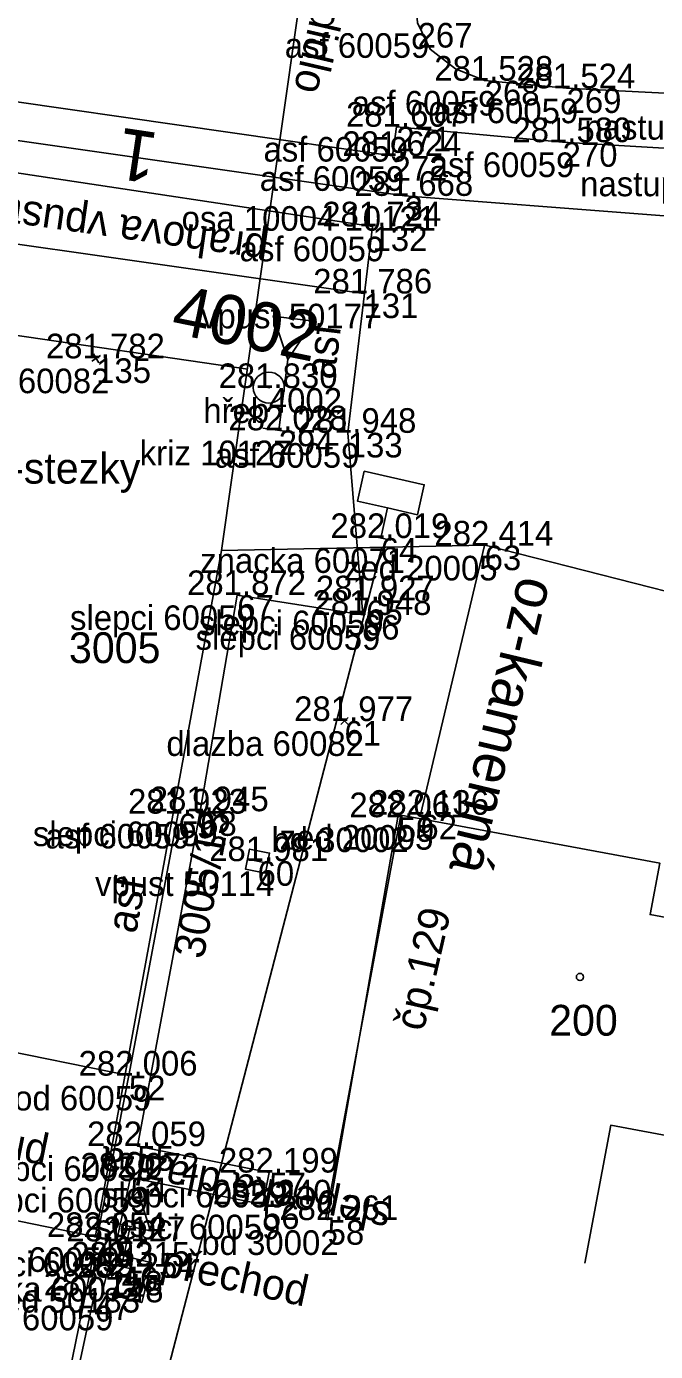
# Model space of a CAD drawing. Extents: x -728659 to -728362, y -1073110 to -1072943.
# Drawn here: x -728507.99 to -728492.66, y -1073071.85 to -1073039.57 of the extents above; entities that cross this region are included whole.
import ezdxf

# ---------------------------------------------------------------- set-up
doc = ezdxf.new("R2010")
doc.units = 0
for name, color, linetype in [('Vrstva 1', 7, 'Continuous'), ('Vrstva 13', 7, 'Continuous'), ('Vrstva 23', 7, 'Continuous'), ('Vrstva 4', 7, 'Continuous'), ('Vrstva 43', 7, 'Continuous'), ('Vrstva 47', 7, 'Continuous'), ('Vrstva 49', 7, 'Continuous'), ('Vrstva 51', 7, 'Continuous'), ('Vrstva 53', 7, 'Continuous'), ('Vrstva 55', 7, 'Continuous'), ('Vrstva 57', 7, 'Continuous'), ('Vrstva 59', 7, 'Continuous'), ('Vrstva 60', 7, 'Continuous'), ('Vrstva 61', 7, 'Continuous'), ('Vrstva 62', 7, 'Continuous'), ('Vrstva 63', 7, 'Continuous')]:
    doc.layers.add(name, color=color, linetype=linetype)

msp = doc.modelspace()

# ---------------------------------------------------------------- linework, layer by layer
at = {"layer": 'Vrstva 1'}
msp.add_lwpolyline([(-728462.112, -1073044.292), (-728486.957, -1073044.611), (-728498.776, -1073043.699), (-728511.695, -1073041.857), (-728514.393, -1073041.361), (-728535.912, -1073035.983), (-728560.369, -1073026.548)], dxfattribs=at)
at = {"layer": 'Vrstva 13'}
msp.add_line((-728496.824, -1073052.218), (-728498.391, -1073058.778), dxfattribs=at)
at = {"layer": 'Vrstva 23'}
msp.add_line((-728500.652, -1073068.652), (-728498.943, -1073058.837), dxfattribs=at)
at = {"layer": 'Vrstva 4'}
msp.add_line((-728502.231, -1073049.36), (-728501.459, -1073049.462), dxfattribs=at)
for points in [[(-728498.776, -1073043.699), (-728511.695, -1073041.857), (-728514.393, -1073041.361)], [(-728501.845, -1073049.411), (-728501.623, -1073047.687), (-728501.984, -1073046.629), (-728500.993, -1073046.754), (-728501.623, -1073047.687)]]:
    msp.add_lwpolyline(points, dxfattribs=at)
at = {"layer": 'Vrstva 43'}
for points in [[(-728499.778, -1073046.077), (-728509.811, -1073044.652), (-728514.235, -1073044.003)], [(-728502.606, -1073059.857), (-728502.556, -1073059.612), (-728502.066, -1073059.712), (-728502.166, -1073060.202), (-728502.656, -1073060.102), (-728502.606, -1073059.857), (-728502.116, -1073059.957)]]:
    msp.add_lwpolyline(points, dxfattribs=at)
at = {"layer": 'Vrstva 47'}
msp.add_lwpolyline([(-728505.905, -1073069.447), (-728504.937, -1073069.695), (-728505.185, -1073070.663), (-728506.153, -1073070.415), (-728505.905, -1073069.447)], dxfattribs=at)
at = {"layer": 'Vrstva 49'}
for p, q in [((-728506.403, -1073047.724), (-728506.191, -1073047.59)), ((-728506.364, -1073047.551), (-728506.23, -1073047.763)), ((-728500.33, -1073056.406), (-728500.154, -1073056.582)), ((-728500.33, -1073056.582), (-728500.154, -1073056.406))]:
    msp.add_line(p, q, dxfattribs=at)
at = {"layer": 'Vrstva 51'}
for p, q in [((-728499.558, -1073044.443), (-728513.906, -1073042.29)), ((-728499.601, -1073051.98), (-728499.113, -1073052.09)), ((-728505.92, -1073069.734), (-728505.432, -1073069.84))]:
    msp.add_line(p, q, dxfattribs=at)
for points in [[(-728496.482, -1073035.776), (-728497.494, -1073036.644), (-728498.316, -1073037.996), (-728498.528, -1073038.603), (-728498.459, -1073039.486), (-728498.149, -1073040.128), (-728497.533, -1073040.603), (-728496.825, -1073040.892), (-728494.827, -1073041.079), (-728486.835, -1073041.479), (-728486.937, -1073042.858), (-728494.923, -1073042.391), (-728498.977, -1073042.014), (-728499.069, -1073042.727), (-728513.553, -1073040.642)], [(-728499.794, -1073053.909), (-728500.162, -1073049.472), (-728499.558, -1073044.443)], [(-728499.357, -1073052.035), (-728499.192, -1073051.303), (-728498.46, -1073051.469), (-728498.295, -1073050.737), (-728499.758, -1073050.407), (-728499.923, -1073051.138), (-728499.192, -1073051.303)], [(-728506.273, -1073069.065), (-728505.797, -1073069.171), (-728505.457, -1073067.617), (-728502.232, -1073068.271), (-728502.075, -1073067.494), (-728505.291, -1073066.851), (-728503.761, -1073058.691), (-728502.856, -1073053.426), (-728499.794, -1073053.909), (-728499.714, -1073053.554)], [(-728505.498, -1073065.132), (-728504.293, -1073058.749)], [(-728505.498, -1073065.132), (-728512.38, -1073063.734), (-728513.171, -1073067.654), (-728506.273, -1073069.065), (-728505.498, -1073065.132)], [(-728505.676, -1073069.787), (-728505.463, -1073068.81), (-728504.975, -1073068.916), (-728505.277, -1073067.955), (-728505.952, -1073068.704), (-728505.463, -1073068.81)], [(-728518.577, -1073107.972), (-728511.413, -1073089.698), (-728508.676, -1073080.788), (-728506.273, -1073069.065)], [(-728518.469, -1073107.966), (-728511.248, -1073089.672), (-728508.568, -1073080.832), (-728506.346, -1073070.488)]]:
    msp.add_lwpolyline(points, dxfattribs=at)
at = {"layer": 'Vrstva 53'}
msp.add_lwpolyline([(-728443.68, -1073014.51), (-728493.68, -1073027.94), (-728497.54, -1073030.15), (-728499.78, -1073032.61), (-728501.19, -1073037.94), (-728503.24, -1073052.34), (-728496.81, -1073052.21), (-728491.97, -1073053.44), (-728477.97, -1073053.19), (-728434.587, -1073049.291), (-728361.73, -1073039.5)], dxfattribs=at)
at = {"layer": 'Vrstva 55'}
for p, q in [((-728502.6, -1073047.92), (-728509.9, -1073046.86)), ((-728506.32, -1073069.08), (-728503.24, -1073052.34)), ((-728504.87, -1073073.55), (-728499.33, -1073052.26))]:
    msp.add_line(p, q, dxfattribs=at)
for points in [[(-728487.98, -1073062.11), (-728492.79, -1073061.21), (-728492.55, -1073059.96), (-728498.42, -1073058.87), (-728498.87, -1073058.79), (-728500.7, -1073068.59)], [(-728494.38, -1073069.7), (-728493.75, -1073066.34), (-728490.32, -1073066.98), (-728489.74, -1073063.94), (-728488.34, -1073064.21), (-728487.98, -1073062.11)]]:
    msp.add_lwpolyline(points, dxfattribs=at)
at = {"layer": 'Vrstva 59'}
msp.add_circle((-728494.5, -1073062.729), 0.0873, dxfattribs=at)
at = {"layer": 'Vrstva 60'}
for p, q in [((-728496.825, -1073040.892), (-728496.825, -1073040.892)), ((-728494.827, -1073041.079), (-728494.827, -1073041.079)), ((-728498.977, -1073042.014), (-728498.977, -1073042.014)), ((-728494.923, -1073042.391), (-728494.923, -1073042.391)), ((-728499.069, -1073042.727), (-728499.069, -1073042.727)), ((-728498.776, -1073043.699), (-728498.776, -1073043.699)), ((-728499.558, -1073044.443), (-728499.558, -1073044.443)), ((-728499.778, -1073046.077), (-728499.778, -1073046.077)), ((-728506.297, -1073047.657), (-728506.297, -1073047.657)), ((-728502.086, -1073048.382), (-728502.086, -1073048.382)), ((-728501.845, -1073049.411), (-728501.845, -1073049.411)), ((-728500.162, -1073049.472), (-728500.162, -1073049.472)), ((-728499.357, -1073052.035), (-728499.357, -1073052.035)), ((-728496.824, -1073052.218), (-728496.824, -1073052.218)), ((-728502.856, -1073053.426), (-728502.856, -1073053.426)), ((-728499.714, -1073053.554), (-728499.714, -1073053.554)), ((-728499.794, -1073053.909), (-728499.794, -1073053.909)), ((-728500.242, -1073056.494), (-728500.242, -1073056.494)), ((-728503.761, -1073058.691), (-728503.761, -1073058.691)), ((-728504.293, -1073058.749), (-728504.293, -1073058.749)), ((-728498.943, -1073058.837), (-728498.943, -1073058.837)), ((-728498.391, -1073058.778), (-728498.391, -1073058.778)), ((-728502.361, -1073059.907), (-728502.361, -1073059.907)), ((-728505.498, -1073065.132), (-728505.498, -1073065.132)), ((-728505.291, -1073066.851), (-728505.291, -1073066.851)), ((-728505.457, -1073067.617), (-728505.457, -1073067.617)), ((-728502.075, -1073067.494), (-728502.075, -1073067.494)), ((-728502.232, -1073068.271), (-728502.232, -1073068.271)), ((-728500.652, -1073068.652), (-728500.652, -1073068.652)), ((-728506.273, -1073069.065), (-728506.273, -1073069.065)), ((-728505.797, -1073069.171), (-728505.797, -1073069.171)), ((-728505.676, -1073069.787), (-728505.676, -1073069.787)), ((-728505.545, -1073070.055), (-728505.545, -1073070.055)), ((-728506.346, -1073070.488), (-728506.346, -1073070.488))]:
    msp.add_line(p, q, dxfattribs=at)
at = {"layer": 'Vrstva 63'}
msp.add_line((-728502.111, -1073048.364), (-728502.061, -1073048.374), dxfattribs=at)
msp.add_circle((-728502.086, -1073048.369), 0.378, dxfattribs=at)

# ---------------------------------------------------------------- texts
at = {"layer": 'Vrstva 1'}
msp.add_text('1', height=1.25, rotation=171.4856, dxfattribs=at).set_placement((-728504.746, -1073042.173))
at = {"layer": 'Vrstva 13'}
msp.add_text('oz-kamenná', height=1, rotation=256.5654, dxfattribs=at).set_placement((-728495.982, -1073052.924))
at = {"layer": 'Vrstva 23'}
msp.add_text('čp.129', height=0.75, rotation=77.1025, dxfattribs=at).set_placement((-728498.315, -1073064.077))
at = {"layer": 'Vrstva 43'}
msp.add_text('prahova vpust š25', height=0.75, rotation=171.9163, dxfattribs=at).set_placement((-728502.097, -1073044.659))
at = {"layer": 'Vrstva 51'}
for s, rotation, p in [('asf', 83.1514, (-728500.483, -1073048.193)), ('asf', 79.3094, (-728505.325, -1073061.695)), ('přechod', 168.5173, (-728507.432, -1073066.758)), ('slepecka dlažba', 168.6935, (-728499.062, -1073068.25))]:
    msp.add_text(s, height=0.75, rotation=rotation, dxfattribs=at).set_placement(p)
at = {"layer": 'Vrstva 57'}
for s, p in [('3005', (-728506.959, -1073055.082)), ('200', (-728495.251, -1073064.159))]:
    msp.add_text(s, height=0.75, dxfattribs=at).set_placement(p)
msp.add_text('3005/13', height=0.75, rotation=79.4989, dxfattribs=at).set_placement((-728503.678, -1073062.314))
at = {"layer": 'Vrstva 60'}
for s, p in [('267', (-728498.459, -1073040.086)), ('268', (-728496.825, -1073041.492)), ('269', (-728494.827, -1073041.679)), ('271', (-728498.977, -1073042.614)), ('270', (-728494.923, -1073042.991)), ('272', (-728499.069, -1073043.327)), ('3', (-728498.776, -1073044.299)), ('132', (-728499.558, -1073045.043)), ('131', (-728499.778, -1073046.677)), ('135', (-728506.297, -1073048.257)), ('4002', (-728502.086, -1073048.982)), ('294', (-728501.845, -1073050.011)), ('133', (-728500.162, -1073050.072)), ('64', (-728499.357, -1073052.635)), ('63', (-728496.824, -1073052.818)), ('67', (-728502.856, -1073054.026)), ('65', (-728499.714, -1073054.154)), ('66', (-728499.794, -1073054.509)), ('61', (-728500.242, -1073057.094)), ('68', (-728503.761, -1073059.291)), ('69', (-728504.293, -1073059.349)), ('59', (-728498.943, -1073059.437)), ('62', (-728498.391, -1073059.378)), ('60', (-728502.361, -1073060.507)), ('52', (-728505.498, -1073065.732)), ('55', (-728505.291, -1073067.451)), ('54', (-728505.457, -1073068.217)), ('57', (-728502.075, -1073068.094)), ('56', (-728502.232, -1073068.871)), ('58', (-728500.652, -1073069.252)), ('49', (-728506.273, -1073069.665)), ('53', (-728505.797, -1073069.771)), ('46', (-728505.676, -1073070.387)), ('48', (-728505.545, -1073070.655)), ('47', (-728506.346, -1073071.088))]:
    msp.add_text(s, height=0.6, dxfattribs=at).set_placement(p)
at = {"layer": 'Vrstva 61'}
for s, p in [('281.528', (-728498.052, -1073040.892)), ('281.524', (-728496.052, -1073041.079)), ('281.607', (-728500.203, -1073042.014)), ('281.580', (-728496.148, -1073042.391)), ('281.624', (-728500.294, -1073042.727)), ('281.668', (-728500.003, -1073043.699)), ('281.724', (-728500.783, -1073044.443)), ('281.786', (-728501.004, -1073046.077)), ('281.782', (-728507.521, -1073047.657)), ('281.830', (-728503.311, -1073048.382)), ('282.028', (-728503.072, -1073049.411)), ('281.948', (-728501.389, -1073049.472)), ('282.019', (-728500.584, -1073052.035)), ('282.414', (-728498.049, -1073052.218)), ('281.872', (-728504.08, -1073053.426)), ('281.927', (-728500.94, -1073053.554)), ('281.948', (-728501.021, -1073053.909)), ('281.977', (-728501.468, -1073056.494)), ('281.923', (-728505.519, -1073058.749)), ('281.945', (-728504.989, -1073058.691)), ('282.061', (-728500.122, -1073058.837)), ('282.136', (-728499.617, -1073058.778)), ('281.981', (-728503.54, -1073059.907)), ('282.006', (-728506.724, -1073065.132)), ('282.059', (-728506.518, -1073066.851)), ('282.072', (-728506.681, -1073067.617)), ('282.199', (-728503.302, -1073067.494)), ('282.240', (-728503.457, -1073068.271)), ('282.261', (-728501.831, -1073068.652)), ('282.054', (-728507.498, -1073069.065)), ('282.127', (-728507.023, -1073069.171)), ('282.215', (-728506.904, -1073069.787)), ('282.254', (-728506.77, -1073070.055)), ('282.158', (-728507.573, -1073070.488))]:
    msp.add_text(s, height=0.6, dxfattribs=at).set_placement(p)
at = {"layer": 'Vrstva 62'}
for s, p in [('asf 60059', (-728501.698, -1073040.336)), ('asf 60059', (-728500.064, -1073041.742)), ('asf 60059', (-728498.066, -1073041.929)), ('nastupiste 20024 60059', (-728494.393, -1073042.329)), ('asf 60059', (-728502.216, -1073042.864)), ('asf 60059', (-728498.162, -1073043.241)), ('asf 60059', (-728502.308, -1073043.577)), ('nastupiste 20024 60059', (-728494.495, -1073043.708)), ('osa 10004 10121', (-728504.212, -1073044.549)), ('asf 60059', (-728502.797, -1073045.293)), ('vpust 50177', (-728503.741, -1073046.927)), ('osa 60082', (-728509.721, -1073048.507)), ('hřeb', (-728503.683, -1073049.232)), ('kriz 10127', (-728505.234, -1073050.261)), ('asf 60059', (-728503.401, -1073050.322)), ('znacka 60071', (-728503.76, -1073052.885)), ('zed 20005', (-728500.256, -1073053.068)), ('slepci 60059', (-728506.934, -1073054.276)), ('slepci 60059', (-728503.792, -1073054.404)), ('slepci 60059', (-728503.872, -1073054.759)), ('dlazba 60082', (-728504.583, -1073057.344)), ('slepci 60059', (-728507.839, -1073059.541)), ('asf 60059', (-728507.532, -1073059.599)), ('zed 20005', (-728501.823, -1073059.628)), ('bd 30002', (-728502.023, -1073059.687)), ('vpust 50114', (-728506.323, -1073060.757)), ('prechod 60059', (-728510.303, -1073065.982)), ('slepci 60059', (-728509.369, -1073067.701)), ('slepci 60059', (-728506.153, -1073068.344)), ('slepci 60059', (-728509.535, -1073068.467)), ('slepci 60059', (-728506.31, -1073069.121)), ('bd 30002', (-728503.732, -1073069.502)), ('prechod 60059', (-728511.078, -1073069.915)), ('slepci 60059', (-728509.875, -1073070.021)), ('znacka 60072', (-728510.17, -1073070.637)), ('zed 50183', (-728508.973, -1073070.905)), ('sachta 60059', (-728510.693, -1073071.338))]:
    msp.add_text(s, height=0.6, dxfattribs=at).set_placement(p)
at = {"layer": 'Vrstva 63'}
for s, height, rotation, p in [('betonové svodidlo', 0.75, 256.9959, (-728499.662, -1073033.23)), ('4002', 1.2, 348.5433, (-728504.503, -1073047.034)), ('přechod', 0.75, 347.7287, (-728504.761, -1073069.991))]:
    msp.add_text(s, height=height, rotation=rotation, dxfattribs=at).set_placement(p)
msp.add_text('cyklo-stezky', height=0.75, dxfattribs=at).set_placement((-728510.679, -1073050.709))

doc.saveas('drawing.dxf')
